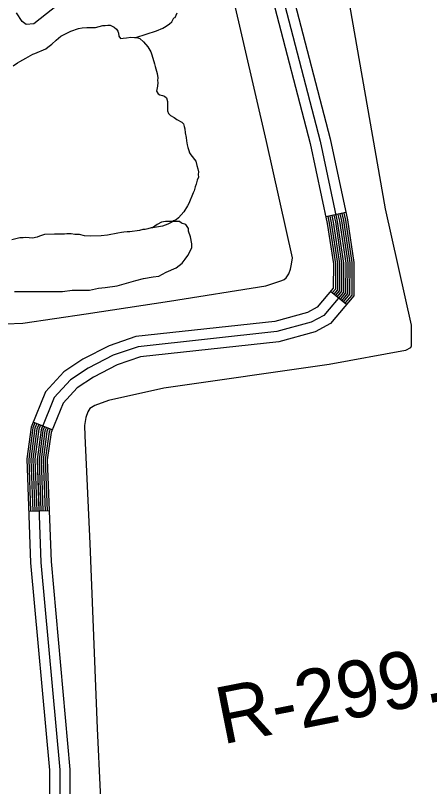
# Model space of a CAD drawing. Extents: x 3161665 to 3199565, y 885729 to 911164.
# Drawn here: x 3182026 to 3182631, y 893776 to 894901 of the extents above; entities that cross this region are included whole.
import ezdxf

# ---------------------------------------------------------------- set-up
doc = ezdxf.new("R2010")
doc.units = 0
for name, color, linetype in [('V-LEVE-TOET', 7, 'Continuous'), ('V-RIVR-RANG-IDEN', 7, 'Continuous'), ('V-ROAD-CNTR', 7, 'Continuous'), ('V-SITE-VEGE', 7, 'Continuous'), ('V-TOPO-SHOR', 7, 'Continuous')]:
    doc.layers.add(name, color=color, linetype=linetype)

msp = doc.modelspace()

# ---------------------------------------------------------------- linework, layer by layer
at = {"layer": 'V-LEVE-TOET'}
for points in [[(3182313.5, 895094), (3182053.3, 894888.4), (3182042.1, 894887.6), (3182036.4, 894891.6), (3182027.8, 894904.4)], [(3182012.3, 894450.8), (3182037.4, 894452.1), (3182129.8, 894465.7), (3182251.4, 894484.2), (3182391.7, 894506.3), (3182415, 894514.2), (3182418.5, 894515.8), (3182421.6, 894518.2), (3182425.2, 894523.9), (3182427.7, 894530.6), (3182429.1, 894538.1), (3182430.5, 894547.2), (3182392.9, 894716.8), (3182343.1, 894931.5)], [(3182513.7, 894915.5), (3182565.9, 894618.7), (3182603.7, 894449.2), (3182603.7, 894418.3), (3182602.8, 894416), (3182595.4, 894412), (3182484.4, 894391.4), (3182243.1, 894357), (3182162.3, 894339.3), (3182142.1, 894331.8), (3182134.9, 894327.5), (3182132.2, 894322.7), (3182128.9, 894314.4), (3182127.1, 894302.7), (3182127.5, 894287.8), (3182134.8, 894130.5), (3182145.5, 893860.9), (3182154.2, 893675.9)]]:
    msp.add_lwpolyline(points, dxfattribs=at)
at = {"layer": 'V-ROAD-CNTR'}
for p, q in [((3182508.7, 894613.2), (3182479.3, 894606.8)), ((3182509.3, 894478.9), (3182486.3, 894498.3)), ((3182079.9, 894296.3), (3182052.1, 894307.7)), ((3182075.6, 894178.4), (3182045.6, 894177.4))]:
    msp.add_line(p, q, dxfattribs=at)
for points in [[(3182357.5, 895224.7), (3182354.3, 895208.8), (3182359.1, 895154.8), (3182368.1, 895084), (3182401.6, 894925.3), (3182456.3, 894713.9), (3182481.4, 894597.4), (3182490.3, 894538.3), (3182490.2, 894502.8), (3182466.9, 894475.2), (3182452.5, 894467.5), (3182405, 894454.4), (3182202.3, 894432.3), (3182163.1, 894419), (3182124.8, 894399.2), (3182097, 894380.7), (3182070.1, 894351.7), (3182049.1, 894300.2), (3182042.8, 894254), (3182048.3, 894102.2), (3182076, 893799.8), (3182076.4, 893721.6)], [(3182416.2, 894928.7), (3182470.9, 894717.4), (3182496.1, 894600.1), (3182505.3, 894539.4), (3182505.1, 894497.3), (3182476.5, 894463.3), (3182458, 894453.5), (3182407.8, 894439.6), (3182205.5, 894417.6), (3182168.9, 894405.2), (3182132.5, 894386.3), (3182106.8, 894369.2), (3182082.9, 894343.5), (3182063.7, 894296.3), (3182057.9, 894253.2), (3182063.3, 894103.1), (3182091, 893800.5), (3182091.4, 893719.7)], [(3182430.8, 894932.2), (3182485.5, 894720.8), (3182510.9, 894602.8), (3182520.3, 894540.5), (3182520.1, 894491.8), (3182486.1, 894451.4), (3182463.6, 894439.5), (3182410.6, 894424.8), (3182208.8, 894402.9), (3182174.8, 894391.3), (3182140.1, 894373.3), (3182116.6, 894357.7), (3182095.8, 894335.3), (3182078.3, 894292.4), (3182072.9, 894252.5), (3182078.3, 894104.1), (3182106, 893801.2), (3182106.4, 893717.9)], [(3182482.3, 894607.5), (3182484.3, 894597.9), (3182493.3, 894538.5), (3182493.2, 894501.7), (3182488.6, 894496.3)], [(3182485.2, 894608.1), (3182487.3, 894598.4), (3182496.3, 894538.7), (3182496.2, 894500.6), (3182490.9, 894494.4)], [(3182488.1, 894608.7), (3182490.2, 894599), (3182499.3, 894539), (3182499.2, 894499.5), (3182493.2, 894492.5)], [(3182491.1, 894609.4), (3182493.2, 894599.5), (3182502.3, 894539.2), (3182502.1, 894498.4), (3182495.5, 894490.5)], [(3182494, 894610), (3182496.1, 894600.1), (3182505.3, 894539.4), (3182505.1, 894497.3), (3182497.8, 894488.6)], [(3182496.9, 894610.6), (3182499.1, 894600.6), (3182508.3, 894539.6), (3182508.1, 894496.2), (3182500.1, 894486.7)], [(3182499.9, 894611.3), (3182502, 894601.1), (3182511.3, 894539.8), (3182511.1, 894495.1), (3182502.4, 894484.7)], [(3182502.8, 894611.9), (3182505, 894601.7), (3182514.3, 894540.1), (3182514.1, 894494), (3182504.7, 894482.8)], [(3182505.7, 894612.5), (3182508, 894602.2), (3182517.3, 894540.3), (3182517.1, 894492.9), (3182507, 894480.9)], [(3182054.9, 894306.5), (3182052, 894299.4), (3182045.8, 894253.8), (3182048.6, 894177.5)], [(3182057.7, 894305.4), (3182054.9, 894298.6), (3182048.8, 894253.7), (3182051.6, 894177.6)], [(3182060.4, 894304.3), (3182057.8, 894297.8), (3182051.9, 894253.5), (3182054.6, 894177.7)], [(3182063.2, 894303.1), (3182060.7, 894297.1), (3182054.9, 894253.4), (3182057.6, 894177.8)], [(3182066, 894302), (3182063.7, 894296.3), (3182057.9, 894253.2), (3182060.6, 894177.9)], [(3182068.8, 894300.9), (3182066.6, 894295.5), (3182060.9, 894253.1), (3182063.6, 894178)], [(3182071.6, 894299.7), (3182069.5, 894294.7), (3182063.9, 894252.9), (3182066.6, 894178.1)], [(3182074.3, 894298.6), (3182072.4, 894293.9), (3182066.9, 894252.8), (3182069.6, 894178.2)], [(3182077.1, 894297.5), (3182075.4, 894293.2), (3182069.9, 894252.6), (3182072.6, 894178.3)]]:
    msp.add_lwpolyline(points, dxfattribs=at)
at = {"layer": 'V-SITE-VEGE'}
for p, q in [((3182259.4, 894897.9), (3182262.2, 894904.5)), ((3182246.3, 894884.8), (3182251, 894888.5)), ((3182251, 894888.5), (3182254.8, 894891.3)), ((3182254.8, 894891.3), (3182257.6, 894897)), ((3182257.6, 894897), (3182259.4, 894897.9)), ((3182097.4, 894873), (3182107.4, 894877.5)), ((3182107.4, 894877.5), (3182118.5, 894881.6)), ((3182118.5, 894881.6), (3182123.6, 894882.7)), ((3182123.6, 894882.7), (3182130.5, 894883)), ((3182130.5, 894883), (3182138.6, 894882.9)), ((3182138.6, 894882.9), (3182143.1, 894883.2)), ((3182143.1, 894883.2), (3182148.8, 894884.3)), ((3182148.8, 894884.3), (3182153.9, 894885.8)), ((3182153.9, 894885.8), (3182157.2, 894886.1)), ((3182157.2, 894886.1), (3182161.1, 894886.7)), ((3182161.1, 894886.7), (3182164.7, 894886.3)), ((3182164.7, 894886.3), (3182170.7, 894883.6)), ((3182170.7, 894883.6), (3182174, 894880.6)), ((3182174, 894880.6), (3182175.8, 894877.8)), ((3182175.8, 894877.8), (3182177, 894874.8)), ((3182201.9, 894868.3), (3182232.3, 894878.2)), ((3182232.3, 894878.2), (3182241.6, 894882)), ((3182241.6, 894882), (3182246.3, 894884.8)), ((3182085.7, 894864.4), (3182092.6, 894870.4)), ((3182092.6, 894870.4), (3182097.4, 894873)), ((3182177, 894874.8), (3182177.5, 894870.3)), ((3182177.5, 894870.3), (3182179.9, 894867)), ((3182179.9, 894867), (3182183.5, 894867.3)), ((3182183.5, 894867.3), (3182188.3, 894868.1)), ((3182188.3, 894868.1), (3182194.6, 894869)), ((3182194.6, 894869), (3182201.9, 894868.3)), ((3182070.9, 894852.2), (3182073.9, 894854.3)), ((3182073.9, 894854.3), (3182079.6, 894858.8)), ((3182079.6, 894858.8), (3182085.7, 894864.4)), ((3182048.6, 894842.2), (3182051.9, 894844.3)), ((3182051.9, 894844.3), (3182054.9, 894845.1)), ((3182054.9, 894845.1), (3182070.9, 894852.2)), ((3182023.3, 894827.4), (3182029.3, 894831.5)), ((3182029.3, 894831.5), (3182032.6, 894833.6)), ((3182032.6, 894833.6), (3182041.7, 894838.6)), ((3182041.7, 894838.6), (3182048.6, 894842.2)), ((3182233, 894595.6), (3182226.4, 894590.9)), ((3182239.5, 894599.4), (3182233, 894595.6)), ((3182245.2, 894600.3), (3182239.5, 894599.4)), ((3182265.8, 894600.3), (3182245.2, 894600.3)), ((3182268.6, 894597.5), (3182265.8, 894600.3)), ((3182275.2, 894595.6), (3182268.6, 894597.5)), ((3182278.9, 894590), (3182275.2, 894595.6)), ((3182181.1, 894584.1), (3182175.7, 894583.2)), ((3182184.4, 894584.4), (3182181.1, 894584.1)), ((3182189.5, 894585.2), (3182184.4, 894584.4)), ((3182193.1, 894585.2), (3182189.5, 894585.2)), ((3182207.2, 894587.2), (3182193.1, 894585.2)), ((3182212.3, 894588.4), (3182207.2, 894587.2)), ((3182215.6, 894588.6), (3182212.3, 894588.4)), ((3182219.8, 894589.5), (3182215.6, 894588.6)), ((3182224.3, 894590.7), (3182219.8, 894589.5)), ((3182226.4, 894590.9), (3182224.3, 894590.7)), ((3182278.9, 894586.2), (3182278.9, 894590)), ((3182281.7, 894577.8), (3182278.9, 894586.2)), ((3182032.8, 894576.5), (3182021.1, 894573.3)), ((3182037.9, 894576.5), (3182032.8, 894576.5)), ((3182041.5, 894576.7), (3182037.9, 894576.5)), ((3182051.4, 894575.8), (3182041.5, 894576.7)), ((3182058, 894577.5), (3182051.4, 894575.8)), ((3182061.6, 894579), (3182058, 894577.5)), ((3182068.9, 894581), (3182061.6, 894579)), ((3182083.3, 894581.8), (3182068.9, 894581)), ((3182098, 894581.7), (3182083.3, 894581.8)), ((3182101.6, 894582.3), (3182098, 894581.7)), ((3182107.6, 894582), (3182101.6, 894582.3)), ((3182113.3, 894581.3), (3182107.6, 894582)), ((3182116.6, 894581.3), (3182113.3, 894581.3)), ((3182119.9, 894581), (3182116.6, 894581.3)), ((3182127, 894579.4), (3182119.9, 894581)), ((3182136.3, 894578.7), (3182127, 894579.4)), ((3182151.6, 894579.5), (3182136.3, 894578.7)), ((3182160.7, 894580.4), (3182151.6, 894579.5)), ((3182175.7, 894583.2), (3182160.7, 894580.4)), ((3182283.6, 894567.5), (3182281.7, 894577.8)), ((3182278, 894550.6), (3182283.6, 894561.9)), ((3182283.6, 894561.9), (3182283.6, 894567.5)), ((3182274.2, 894545), (3182278, 894550.6)), ((3182261.1, 894532.8), (3182269.5, 894539.4)), ((3182269.5, 894539.4), (3182274.2, 894545)), ((3182246.1, 894526.2), (3182261.1, 894532.8)), ((3182202.1, 894514), (3182213.3, 894516.9)), ((3182213.3, 894516.9), (3182227.4, 894519.7)), ((3182227.4, 894519.7), (3182235.8, 894520.6)), ((3182235.8, 894520.6), (3182246.1, 894526.2)), ((3182157.1, 894503.7), (3182174.9, 894506.5)), ((3182174.9, 894506.5), (3182202.1, 894514)), ((3182024.9, 894498.1), (3182095.2, 894498.1)), ((3182095.2, 894498.1), (3182109.3, 894500)), ((3182109.3, 894500), (3182134.6, 894500)), ((3182134.6, 894500), (3182147.7, 894502.8)), ((3182147.7, 894502.8), (3182157.1, 894503.7))]:
    msp.add_line(p, q, dxfattribs=at)
at = {"layer": 'V-TOPO-SHOR'}
for points in [[(3182023.3, 894827.4), (3182029.3, 894831.5), (3182032.6, 894833.6), (3182041.7, 894838.6), (3182048.6, 894842.2), (3182051.9, 894844.3), (3182054.9, 894845.1), (3182070.9, 894852.2), (3182073.9, 894854.3), (3182079.6, 894858.8), (3182085.7, 894864.4), (3182092.6, 894870.4), (3182097.4, 894873), (3182107.4, 894877.5), (3182118.5, 894881.6), (3182123.6, 894882.7), (3182130.5, 894883), (3182138.6, 894882.9), (3182143.1, 894883.2), (3182148.8, 894884.3), (3182153.9, 894885.8), (3182157.2, 894886.1), (3182161.1, 894886.7), (3182164.7, 894886.3), (3182170.7, 894883.6), (3182174, 894880.6), (3182175.8, 894877.8), (3182177, 894874.8), (3182177.5, 894870.3), (3182179.9, 894867), (3182183.5, 894867.3), (3182188.3, 894868.1), (3182194.6, 894869), (3182204.8, 894868), (3182208.1, 894866.8), (3182213.5, 894862.3), (3182219.4, 894855), (3182223.8, 894847.5), (3182225.6, 894843), (3182229.4, 894830.3), (3182230.3, 894826.1)], [(3182230.3, 894826.1), (3182233.2, 894815.9), (3182234.1, 894809.6), (3182233.7, 894806), (3182234.3, 894802.7), (3182233.7, 894797.3), (3182232.4, 894790.4), (3182234.5, 894786.5), (3182237.2, 894785), (3182241.1, 894784.1), (3182244.1, 894782.8), (3182247, 894780.7), (3182248.5, 894775), (3182248.4, 894761.5), (3182249.9, 894757.9), (3182252.9, 894754.9), (3182258.2, 894751.8), (3182261.8, 894749.1), (3182269, 894744.8), (3182271.4, 894742.4), (3182272.8, 894738.5), (3182273.4, 894735.5), (3182274, 894729.5), (3182275.7, 894722.9), (3182276, 894717.8), (3182277.1, 894712.1), (3182278, 894708.2), (3182279.5, 894703.7), (3182280.3, 894700.4), (3182282.4, 894697.3), (3182289.6, 894688), (3182291.3, 894682), (3182292.5, 894676.9), (3182293.3, 894672.4), (3182293, 894668.5), (3182293.3, 894664.9), (3182291.7, 894660.4), (3182290.2, 894654.4), (3182288.7, 894650.5), (3182287.4, 894645.1), (3182285.6, 894641.8), (3182279.2, 894626.6), (3182277.4, 894623), (3182271.9, 894614.3), (3182264.3, 894605.7), (3182260.7, 894602.7), (3182257.1, 894600.9), (3182254.4, 894599.2), (3182249, 894596.2), (3182241.2, 894593.6), (3182229.4, 894591.2), (3182224.3, 894590.7), (3182219.8, 894589.5), (3182215.6, 894588.6), (3182212.3, 894588.4), (3182207.2, 894587.2), (3182193.1, 894585.2), (3182189.5, 894585.2), (3182184.4, 894584.4), (3182181.1, 894584.1), (3182175.7, 894583.2), (3182160.7, 894580.4), (3182151.6, 894579.5), (3182136.3, 894578.7), (3182127, 894579.4), (3182119.9, 894581), (3182116.6, 894581.3), (3182113.3, 894581.3), (3182107.6, 894582), (3182101.6, 894582.3), (3182098, 894581.7), (3182083.3, 894581.8), (3182068.9, 894581), (3182061.6, 894579), (3182058, 894577.5), (3182051.4, 894575.8), (3182041.5, 894576.7), (3182037.9, 894576.5), (3182032.8, 894576.5), (3182021.1, 894573.3)]]:
    msp.add_lwpolyline(points, dxfattribs=at)

# ---------------------------------------------------------------- texts
at = {"layer": 'V-RIVR-RANG-IDEN'}
msp.add_text('R-299.7', height=83, rotation=11.2251, dxfattribs=at).set_placement((3182328.4, 893837.4))

doc.saveas('drawing.dxf')
